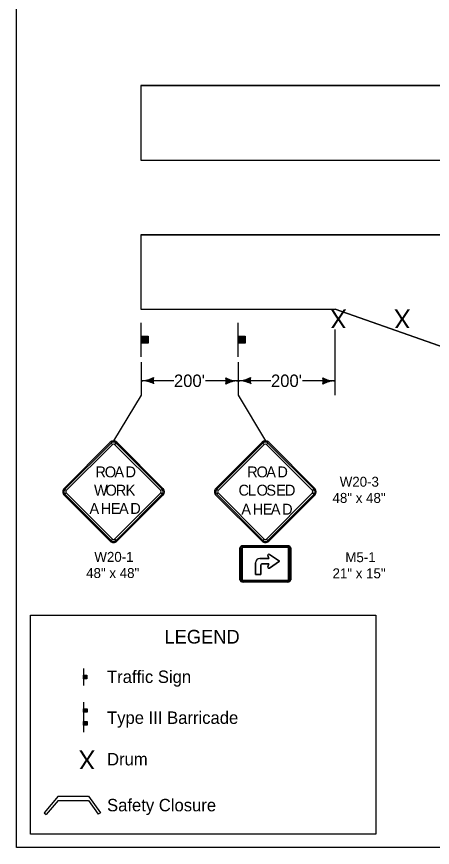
# Model space of a CAD drawing. Extents: x 10133 to 81668, y 7924 to 11018.
# Drawn here: x 10133 to 10801, y 7924 to 9260 of the extents above; entities that cross this region are included whole.
import ezdxf

# ---------------------------------------------------------------- set-up
doc = ezdxf.new("R2010")
doc.units = 0
for name, color, linetype in [('dsnStdBlock', 7, 'Continuous'), ('dsnStdBlockModified', 7, 'Continuous'), ('dsnstdModifiedBlock', 7, 'Continuous')]:
    doc.layers.add(name, color=color, linetype=linetype)

msp = doc.modelspace()

# ---------------------------------------------------------------- linework, layer by layer
at = {"layer": 'dsnStdBlock'}
for p, q in [((10332.5, 9149.3), (10332.5, 9029.3)), ((10332.5, 8909.3), (10332.5, 8789.3)), ((10332.5, 8767.7), (10332.5, 8712.7)), ((10488.6, 8767.7), (10488.6, 8712.7)), ((10645, 8651.1), (10645, 8757.1)), ((10333.3, 8734.8), (10333.3, 8746)), ((10333.9, 8746), (10333.9, 8734.8)), ((10334.4, 8734.8), (10334.4, 8746)), ((10334.9, 8746), (10334.9, 8734.8)), ((10335.4, 8734.8), (10335.4, 8746)), ((10335.8, 8746), (10335.8, 8734.8)), ((10336.5, 8734.8), (10336.5, 8746)), ((10337, 8746), (10337, 8734.8)), ((10337.4, 8734.8), (10337.4, 8746)), ((10338.1, 8746), (10338.1, 8734.8)), ((10338.8, 8734.8), (10338.8, 8746)), ((10339.7, 8746), (10339.7, 8734.8)), ((10340.1, 8734.8), (10340.1, 8746)), ((10341, 8746), (10341, 8734.8)), ((10341.4, 8734.8), (10341.4, 8746)), ((10342, 8746), (10342, 8734.8)), ((10342.5, 8734.8), (10342.5, 8746)), ((10343.1, 8746), (10343.1, 8734.8)), ((10489.4, 8734.8), (10489.4, 8746)), ((10490, 8746), (10490, 8734.8)), ((10490.5, 8734.8), (10490.5, 8746)), ((10491, 8746), (10491, 8734.8)), ((10491.5, 8734.8), (10491.5, 8746)), ((10491.9, 8746), (10491.9, 8734.8)), ((10492.6, 8734.8), (10492.6, 8746)), ((10493.1, 8746), (10493.1, 8734.8)), ((10493.5, 8734.8), (10493.5, 8746)), ((10494.2, 8746), (10494.2, 8734.8)), ((10494.9, 8734.8), (10494.9, 8746)), ((10495.8, 8746), (10495.8, 8734.8)), ((10496.2, 8734.8), (10496.2, 8746)), ((10497, 8746), (10497.1, 8734.8)), ((10497.5, 8734.8), (10497.5, 8746)), ((10498.1, 8746), (10498.1, 8734.8)), ((10498.6, 8734.8), (10498.6, 8746)), ((10499.2, 8746), (10499.2, 8734.8)), ((10332.8, 8704.4), (10332.8, 8651.1)), ((10488.9, 8704.4), (10488.9, 8651.1)), ((10332.8, 8674.4), (10352, 8674.7)), ((10332.8, 8674.4), (10342.5, 8674.6)), ((10385.6, 8674.4), (10332.8, 8674.4)), ((10488.9, 8674.4), (10436.2, 8674.4)), ((10488.9, 8674.4), (10469.7, 8674.1)), ((10488.9, 8674.4), (10479.2, 8674.2)), ((10488.9, 8674.4), (10508.1, 8674.7)), ((10488.9, 8674.4), (10498.6, 8674.6)), ((10541.7, 8674.4), (10488.9, 8674.4)), ((10645, 8674.4), (10592.3, 8674.4)), ((10645, 8674.4), (10625.8, 8674.1)), ((10645, 8674.4), (10635.3, 8674.2)), ((10332.8, 8651.1), (10288.5, 8577.7)), ((10488.9, 8651.1), (10532.7, 8577.7)), ((10239.9, 8211.7), (10239.9, 8184.2)), ((10240.3, 8195.3), (10240.3, 8200.9)), ((10240.6, 8200.9), (10240.6, 8195.3)), ((10240.9, 8195.3), (10240.9, 8200.9)), ((10241.1, 8200.9), (10241.1, 8195.3)), ((10241.3, 8195.3), (10241.3, 8200.9)), ((10241.5, 8200.9), (10241.5, 8195.3)), ((10241.9, 8195.3), (10241.9, 8200.9)), ((10242.1, 8200.9), (10242.1, 8195.3)), ((10242.4, 8195.3), (10242.4, 8200.9)), ((10242.7, 8200.9), (10242.7, 8195.3)), ((10243.1, 8195.3), (10243.1, 8200.9)), ((10243.5, 8200.9), (10243.5, 8195.3)), ((10243.7, 8195.3), (10243.7, 8200.9)), ((10244.1, 8200.9), (10244.2, 8195.3)), ((10244.4, 8195.3), (10244.4, 8200.9)), ((10244.7, 8200.9), (10244.7, 8195.3)), ((10244.9, 8195.3), (10244.9, 8200.9)), ((10245.2, 8200.9), (10245.2, 8195.3)), ((10240.2, 8157.6), (10240.2, 8109.5)), ((10240.5, 8141.3), (10240.5, 8146.9)), ((10240.8, 8146.9), (10240.8, 8141.3)), ((10241.1, 8141.3), (10241.1, 8146.9)), ((10241.3, 8146.9), (10241.3, 8141.3)), ((10241.5, 8141.3), (10241.5, 8146.9)), ((10241.7, 8146.9), (10241.7, 8141.3)), ((10242.1, 8141.3), (10242.1, 8146.9)), ((10242.3, 8146.9), (10242.3, 8141.3)), ((10242.6, 8141.3), (10242.6, 8146.9)), ((10242.9, 8146.9), (10242.9, 8141.3)), ((10243.3, 8141.3), (10243.3, 8146.9)), ((10243.7, 8146.9), (10243.7, 8141.3)), ((10243.9, 8141.3), (10243.9, 8146.9)), ((10244.3, 8146.9), (10244.4, 8141.3)), ((10244.6, 8141.3), (10244.6, 8146.9)), ((10244.9, 8146.9), (10244.9, 8141.3)), ((10245.1, 8141.3), (10245.1, 8146.9)), ((10245.4, 8146.9), (10245.4, 8141.3)), ((10240.5, 8120.6), (10240.5, 8126.2)), ((10240.8, 8126.2), (10240.8, 8120.6)), ((10241.1, 8120.6), (10241.1, 8126.2)), ((10241.3, 8126.2), (10241.3, 8120.6)), ((10241.5, 8120.6), (10241.5, 8126.2)), ((10241.7, 8126.2), (10241.7, 8120.6)), ((10242.1, 8120.6), (10242.1, 8126.2)), ((10242.3, 8126.2), (10242.3, 8120.6)), ((10242.6, 8120.6), (10242.6, 8126.2)), ((10242.9, 8126.2), (10242.9, 8120.6)), ((10243.3, 8120.6), (10243.3, 8126.2)), ((10243.7, 8126.2), (10243.7, 8120.6)), ((10243.9, 8120.6), (10243.9, 8126.2)), ((10244.3, 8126.2), (10244.4, 8120.6)), ((10244.6, 8120.6), (10244.6, 8126.2)), ((10244.9, 8126.2), (10244.9, 8120.6)), ((10245.1, 8120.6), (10245.1, 8126.2)), ((10245.4, 8126.2), (10245.4, 8120.6))]:
    msp.add_line(p, q, dxfattribs=at)
for points in [[(11540, 9149.3), (10332.5, 9149.3), (10332.5, 9029.3), (11480, 9029.3)], [(11480, 8909.3), (10332.5, 8909.3), (10332.5, 8789.3), (10644.7, 8789.3), (10986.3, 8669.3), (11540, 8669.3)], [(10351.6, 8678.3), (10350.9, 8674.7), (10351.7, 8671.1), (10347.4, 8673.1), (10340.6, 8674.5), (10347.9, 8676.4), (10351, 8677.8), (10350.3, 8674.7), (10350.6, 8672.4), (10347.8, 8673.7), (10344, 8674.6), (10348, 8675.8), (10350.1, 8676.6), (10349.7, 8673.5), (10346.9, 8674.6), (10349.1, 8675.4), (10349.1, 8674.3), (10348.1, 8674.6)], [(10470.2, 8670.5), (10470.8, 8674.1), (10470, 8677.7), (10474.3, 8675.7), (10481.2, 8674.3), (10473.9, 8672.5), (10470.8, 8671), (10471.5, 8674.1), (10471.1, 8676.4), (10474, 8675.1), (10477.8, 8674.2), (10473.8, 8673), (10471.7, 8672.2), (10472, 8675.3), (10474.8, 8674.2), (10472.7, 8673.5), (10472.6, 8674.5), (10473.6, 8674.2)], [(10507.7, 8678.3), (10507, 8674.7), (10507.8, 8671.1), (10503.5, 8673.1), (10496.7, 8674.5), (10504, 8676.4), (10507.1, 8677.8), (10506.4, 8674.7), (10506.7, 8672.4), (10503.9, 8673.7), (10500.1, 8674.6), (10504.1, 8675.8), (10506.2, 8676.6), (10505.8, 8673.5), (10503, 8674.6), (10505.2, 8675.4), (10505.2, 8674.3), (10504.2, 8674.6)], [(10626.3, 8670.5), (10626.9, 8674.1), (10626.1, 8677.7), (10630.4, 8675.7), (10637.3, 8674.3), (10630, 8672.5), (10626.8, 8671), (10627.6, 8674.1), (10627.2, 8676.4), (10630.1, 8675.1), (10633.9, 8674.2), (10629.9, 8673), (10627.8, 8672.2), (10628.1, 8675.3), (10630.9, 8674.2), (10628.8, 8673.5), (10628.7, 8674.5), (10629.7, 8674.2)]]:
    msp.add_lwpolyline(points, dxfattribs=at)
for points in [[(10332.7, 8734.8), (10332.7, 8746), (10343.9, 8746), (10343.9, 8734.8)], [(10488.8, 8734.8), (10488.8, 8746), (10500, 8746), (10500, 8734.8)], [(10154.9, 8297.7), (10710.6, 8297.7), (10710.6, 7945.1), (10154.9, 7945.1)], [(10240, 8195.3), (10240, 8200.9), (10245.6, 8200.9), (10245.6, 8195.3)], [(10240.2, 8141.3), (10240.2, 8146.9), (10245.8, 8146.9), (10245.8, 8141.3)], [(10240.2, 8120.6), (10240.2, 8126.3), (10245.8, 8126.3), (10245.8, 8120.6)]]:
    msp.add_lwpolyline(points, close=True, dxfattribs=at)
for centre, radius, start, end in [((10332.1, 8716.9), 42.5, 271, 299.0725), ((10333.6, 8631.9), 42.5, 62.9275, 91), ((10368.5, 8675), 16.4, 163.2666, 198.7334), ((10488.2, 8716.9), 42.5, 242.9275, 271), ((10453.3, 8673.8), 16.4, 343.2666, 18.7334), ((10489.7, 8631.9), 42.5, 91, 119.0725), ((10488.2, 8716.9), 42.5, 271, 299.0725), ((10489.7, 8631.9), 42.5, 62.9275, 91), ((10524.6, 8675), 16.4, 163.2666, 198.7334), ((10644.3, 8716.9), 42.5, 242.9275, 271), ((10609.4, 8673.8), 16.4, 343.2666, 18.7334), ((10645.8, 8631.9), 42.5, 91, 119.0725)]:
    msp.add_arc(centre, radius, start, end, dxfattribs=at)
at = {"layer": 'dsnStdBlockModified'}
for p, q in [((10283.2, 8575.5), (10208.9, 8501.2)), ((10284.5, 8574.2), (10286.7, 8571.9)), ((10290.2, 8571.9), (10292.4, 8574.2)), ((10368, 8501.2), (10293.8, 8575.5)), ((10527.4, 8575.5), (10453.1, 8501.2)), ((10528.7, 8574.2), (10530.9, 8571.9)), ((10534.4, 8571.9), (10536.7, 8574.2)), ((10612.2, 8501.2), (10538, 8575.5)), ((10212.4, 8497.7), (10210.2, 8499.9)), ((10366.7, 8499.9), (10364.5, 8497.7)), ((10456.7, 8497.7), (10454.5, 8499.9)), ((10610.9, 8499.9), (10608.7, 8497.7)), ((10208.9, 8490.6), (10283.2, 8416.4)), ((10210.2, 8492), (10212.4, 8494.2)), ((10293.8, 8416.4), (10368, 8490.6)), ((10364.5, 8494.2), (10366.7, 8492)), ((10453.1, 8490.6), (10527.4, 8416.4)), ((10454.5, 8492), (10456.7, 8494.2)), ((10538, 8416.4), (10612.2, 8490.6)), ((10608.7, 8494.2), (10610.9, 8492)), ((10286.7, 8419.9), (10284.5, 8417.7)), ((10292.4, 8417.7), (10290.2, 8419.9)), ((10530.9, 8419.9), (10528.7, 8417.7)), ((10536.7, 8417.7), (10534.4, 8419.9)), ((10491.8, 8405.5), (10491.8, 8354.4)), ((10491.8, 8354.4), (10491.8, 8405.5)), ((10493.2, 8354.4), (10493.2, 8405.5)), ((10493.2, 8405.5), (10493.2, 8354.4)), ((10495.2, 8405.5), (10495.2, 8354.4)), ((10495.2, 8354.4), (10495.2, 8405.5)), ((10568.4, 8409.2), (10496.9, 8409.2)), ((10496.9, 8409.2), (10568.4, 8409.2)), ((10496.9, 8408.2), (10568.4, 8408.2)), ((10568.4, 8408.2), (10496.9, 8408.2)), ((10568.4, 8406.8), (10496.9, 8406.8)), ((10568.4, 8406.8), (10496.9, 8406.8)), ((10496.9, 8406.8), (10568.4, 8406.8)), ((10570.1, 8354.4), (10570.1, 8405.5)), ((10570.1, 8354.4), (10570.1, 8405.5)), ((10570.1, 8405.5), (10570.1, 8354.4)), ((10572.1, 8405.5), (10572.1, 8354.4)), ((10572.1, 8354.4), (10572.1, 8405.5)), ((10573.6, 8354.4), (10573.6, 8405.5)), ((10573.6, 8405.5), (10573.6, 8354.4)), ((10496.9, 8353.2), (10568.4, 8353.2)), ((10568.4, 8353.2), (10496.9, 8353.2)), ((10568.4, 8351.8), (10496.9, 8351.8)), ((10496.9, 8351.8), (10568.4, 8351.8)), ((10496.9, 8350.8), (10568.4, 8350.8)), ((10568.4, 8350.8), (10496.9, 8350.8)), ((10199.2, 8006.4), (10176.8, 7979.7)), ((10199.2, 8006.4), (10248.4, 8006.4)), ((10248.4, 8006.4), (10267.4, 7979.6)), ((10199.2, 7999.5), (10180.3, 7976.9)), ((10199.2, 7999.5), (10248.4, 7999.5)), ((10248.4, 7999.5), (10263.9, 7977.6)), ((10176.8, 7979.7), (10180.3, 7976.9)), ((10267.4, 7979.6), (10263.9, 7977.6))]:
    msp.add_line(p, q, dxfattribs=at)
for points in [[(10284.5, 8574.2), (10210.2, 8499.9), (10212.4, 8497.7), (10286.7, 8571.9), (10284.5, 8574.2)], [(10366.7, 8499.9), (10292.4, 8574.2), (10290.2, 8571.9), (10364.5, 8497.7), (10366.7, 8499.9)], [(10528.7, 8574.2), (10454.5, 8499.9), (10456.7, 8497.7), (10530.9, 8571.9), (10528.7, 8574.2)], [(10610.9, 8499.9), (10536.7, 8574.2), (10534.4, 8571.9), (10608.7, 8497.7), (10610.9, 8499.9)], [(10210.2, 8492), (10284.5, 8417.7), (10286.7, 8419.9), (10212.4, 8494.2), (10210.2, 8492)], [(10292.4, 8417.7), (10366.7, 8492), (10364.5, 8494.2), (10290.2, 8419.9), (10292.4, 8417.7)], [(10454.5, 8492), (10528.7, 8417.7), (10530.9, 8419.9), (10456.7, 8494.2), (10454.5, 8492)], [(10536.7, 8417.7), (10610.9, 8492), (10608.7, 8494.2), (10534.4, 8419.9), (10536.7, 8417.7)]]:
    msp.add_lwpolyline(points, close=True, dxfattribs=at)
for points in [[(10523.6, 8388.4), (10538.4, 8388.4), (10536.8, 8393.3)], [(10536.8, 8393.3), (10538.4, 8388.4), (10523.6, 8388.4)], [(10539.4, 8395.2), (10555.4, 8384.2), (10539.4, 8373.2)], [(10539.4, 8373.2), (10555.4, 8384.2), (10539.4, 8395.2)], [(10525.3, 8378.3), (10525.3, 8363.1), (10516.9, 8363.1), (10516.9, 8381.7)], [(10516.9, 8381.7), (10516.9, 8363.1), (10525.3, 8363.1), (10525.3, 8378.3)], [(10536.8, 8375.1), (10538.4, 8380), (10527, 8380)], [(10527, 8380), (10538.4, 8380), (10536.8, 8375.1)]]:
    msp.add_lwpolyline(points, dxfattribs=at)
for centre, radius, start, end in [((10288.5, 8570.2), 7.5, 45, 134.9997), ((10532.7, 8570.2), 7.5, 45, 134.9997), ((10288.5, 8570.2), 5.62, 45, 134.9997), ((10288.5, 8570.2), 2.5, 45, 134.9997), ((10532.7, 8570.2), 5.62, 45, 134.9997), ((10532.7, 8570.2), 2.5, 45, 134.9997), ((10214.2, 8495.9), 7.5, 134.9997, 225), ((10214.2, 8495.9), 5.62, 134.9997, 225), ((10214.2, 8495.9), 2.5, 134.9997, 225), ((10362.7, 8495.9), 2.5, 315.0002, 44.9998), ((10362.7, 8495.9), 5.62, 315.0002, 44.9998), ((10362.7, 8495.9), 7.5, 315.0002, 44.9998), ((10458.4, 8495.9), 7.5, 134.9997, 225), ((10458.4, 8495.9), 5.62, 134.9997, 225), ((10458.4, 8495.9), 2.5, 134.9997, 225), ((10606.9, 8495.9), 2.5, 315.0002, 44.9998), ((10606.9, 8495.9), 5.62, 315.0002, 44.9998), ((10606.9, 8495.9), 7.5, 315.0002, 44.9998), ((10288.5, 8421.7), 5.62, 225, 315.0002), ((10288.5, 8421.7), 2.5, 225, 315.0002), ((10532.7, 8421.7), 5.62, 225, 315.0002), ((10532.7, 8421.7), 2.5, 225, 315.0002), ((10288.5, 8421.7), 7.5, 225, 315.0002), ((10532.7, 8421.7), 7.5, 225, 315.0002), ((10538.4, 8393.8), 1.68, 55.5945, 197.9164), ((10538.4, 8393.8), 1.68, 55.5945, 197.9164), ((10523.6, 8381.7), 6.7, 90, 180), ((10523.6, 8381.7), 6.7, 90, 180), ((10527, 8378.3), 1.68, 90, 180), ((10527, 8378.3), 1.68, 90, 180), ((10538.4, 8374.5), 1.68, 162.0836, 304.4055), ((10538.4, 8374.5), 1.68, 162.0836, 304.4055)]:
    msp.add_arc(centre, radius, start, end, dxfattribs=at)
for centre, major_axis, start_param, end_param in [((10496.9, 8405.5), (-5.11, 0), 4.712389, 6.283185), ((10496.9, 8405.5), (-5.11, 0), 4.712389, 6.283185), ((10496.9, 8405.5), (-3.69, 0), 4.712389, 6.283185), ((10496.9, 8405.5), (-3.69, 0), 4.712389, 6.283185), ((10496.9, 8405.5), (-1.7, 0), 4.712389, 6.283185), ((10496.9, 8405.5), (-1.7, 0), 4.712389, 6.283185), ((10568.4, 8405.5), (5.11, 0), 0, 1.570796), ((10568.4, 8405.5), (5.11, 0), 0, 1.570796), ((10568.4, 8405.5), (3.69, 0), 0, 1.570796), ((10568.4, 8405.5), (3.69, 0), 0, 1.570796), ((10568.4, 8405.5), (1.7, 0), 0, 1.570796), ((10568.4, 8405.5), (1.7, 0), 0, 1.570796), ((10568.4, 8405.5), (1.7, 0), 0, 1.570796), ((10496.9, 8354.4), (-5.11, 0), 0, 1.570796), ((10496.9, 8354.4), (-5.11, 0), 0, 1.570796), ((10496.9, 8354.4), (-3.69, 0), 0, 1.570796), ((10496.9, 8354.4), (-3.69, 0), 0, 1.570796), ((10496.9, 8354.4), (-1.7, 0), 0, 1.570796), ((10496.9, 8354.4), (-1.7, 0), 0, 1.570796), ((10568.4, 8354.4), (1.7, 0), 4.712389, 6.283185), ((10568.4, 8354.4), (5.11, 0), 4.712389, 6.283185), ((10568.4, 8354.4), (3.69, 0), 4.712389, 6.283185), ((10568.4, 8354.4), (1.7, 0), 4.712389, 6.283185), ((10568.4, 8354.4), (5.11, 0), 4.712389, 6.283185), ((10568.4, 8354.4), (3.69, 0), 4.712389, 6.283185), ((10568.4, 8354.4), (1.7, 0), 4.712389, 6.283185)]:
    msp.add_ellipse(centre, major_axis=major_axis, ratio=0.714286, start_param=start_param, end_param=end_param, dxfattribs=at)
at = {"layer": 'dsnstdModifiedBlock'}
for p, q in [((10332.5, 9149.3), (11540, 9149.3)), ((10332.5, 9029.3), (11480, 9029.3)), ((10332.5, 8909.3), (11480, 8909.3)), ((10332.5, 8789.3), (10644.7, 8789.3)), ((10986.3, 8669.3), (10644.7, 8789.3))]:
    msp.add_line(p, q, dxfattribs=at)
msp.add_lwpolyline([(10132.5, 9944), (13267.5, 9944), (13267.5, 7924), (10132.5, 7924)], close=True, dxfattribs=at)

# ---------------------------------------------------------------- texts
at = {"layer": 'dsnStdBlock'}
for p in [(10663.6, 8789.3), (10766.3, 8789.3), (10259.1, 8080.2)]:
    msp.add_text('X', height=30, rotation=180, dxfattribs=at).set_placement(p)
for s, height, p in [('LEGEND', 22, (10370.4, 8251.8)), ('Traffic Sign', 20, (10278, 8188.4)), ('Type III Barricade ', 20, (10278, 8122.6)), ('Drum', 20, (10278, 8055.9)), ('Safety Closure', 20, (10278, 7982))]:
    msp.add_text(s, height=height, dxfattribs=at).set_placement(p)
at = {"layer": 'dsnStdBlockModified'}
for s, height, p in [("200'", 20, (10385.6, 8664.4)), ("200'", 20, (10541.7, 8664.4)), ('R', 17.5, (10259.3, 8519.1)), ('O', 17.5, (10274.3, 8519.1)), ('A', 17.5, (10289.9, 8519.1)), ('D', 17.5, (10307.7, 8519.1)), ('R', 17.5, (10503.5, 8519.1)), ('O', 17.5, (10518.5, 8519.1)), ('A', 17.5, (10534.1, 8519.1)), ('D', 17.5, (10552, 8519.1)), ('W20-3', 16, (10652.3, 8504)), ('W', 17.5, (10257, 8489.7)), ('O', 17.5, (10275.6, 8489.7)), ('R', 17.5, (10292, 8489.7)), ('K', 17.5, (10307.9, 8489.7)), ('C', 17.5, (10489.5, 8489.7)), ('L', 17.5, (10504.6, 8489.7)), ('O', 17.5, (10518.6, 8489.7)), ('S', 17.5, (10534.2, 8489.7)), ('E', 17.5, (10550.1, 8489.7)), ('D', 17.5, (10564.1, 8489.7)), ('48" x 48"', 16, (10640.7, 8478)), ('A', 17.5, (10249.7, 8460.3)), ('H', 17.5, (10267.9, 8460.3)), ('E', 17.5, (10284.2, 8460.3)), ('A', 17.5, (10297.2, 8460.3)), ('D', 17.5, (10315.4, 8460.3)), ('A', 17.5, (10494, 8459.1)), ('H', 17.5, (10512.2, 8459.1)), ('E', 17.5, (10528.4, 8459.1)), ('A', 17.5, (10541.4, 8459.1)), ('D', 17.5, (10559.6, 8459.1)), ('W20-1', 16, (10257.6, 8383.2)), ('M5-1', 16, (10661.3, 8382.7)), ('48" x 48"', 16, (10244.4, 8357.2)), ('21" x 15"', 16, (10640.7, 8356.7))]:
    msp.add_text(s, height=height, dxfattribs=at).set_placement(p)

doc.saveas('drawing.dxf')
